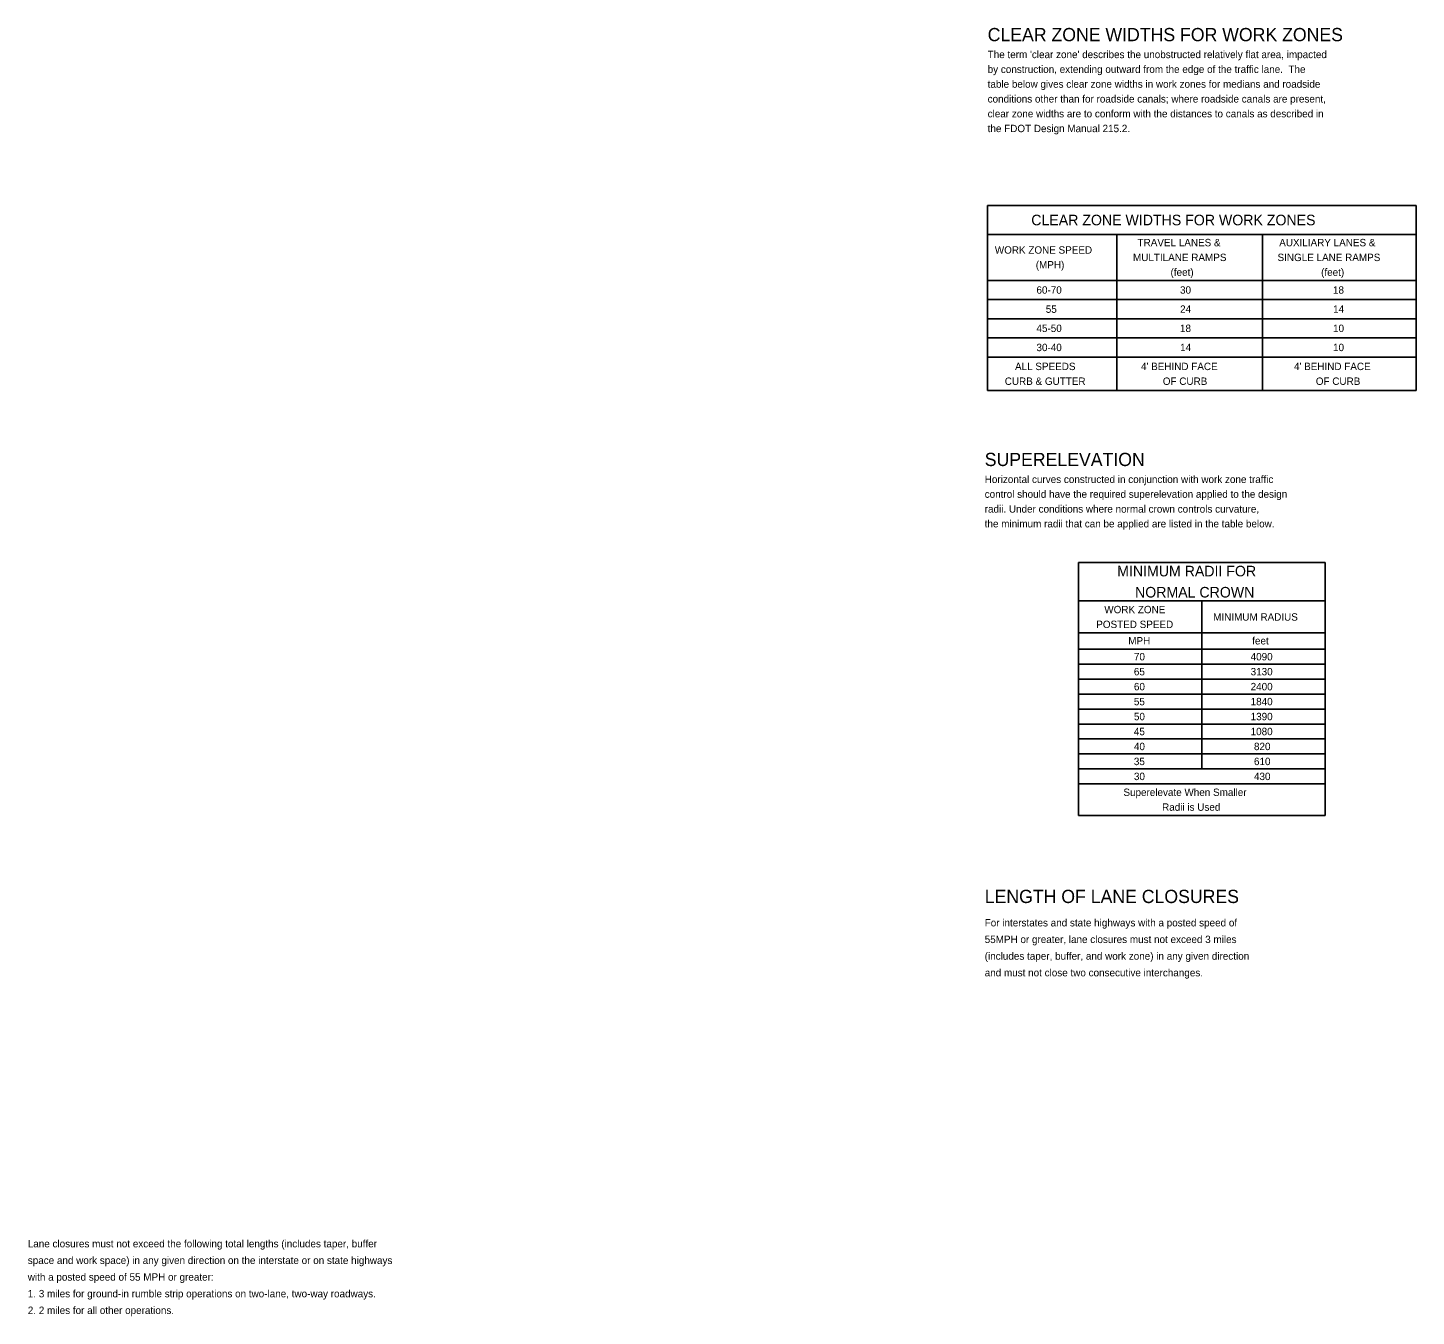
# Model space of a CAD drawing. Extents: x 9589 to 10706, y 9894 to 10509.
# Drawn here: x 9589 to 10246, y 9894 to 10504 of the extents above; entities that cross this region are included whole.
import ezdxf

# ---------------------------------------------------------------- set-up
doc = ezdxf.new("R2010")
doc.units = 0
doc.layers.add('PlotBorder_dp', color=7, linetype='Continuous')

msp = doc.modelspace()

# ---------------------------------------------------------------- linework, layer by layer
at = {"layer": 'PlotBorder_dp'}
for p, q in [((10246.24, 10419.67), (10043.48, 10419.67)), ((10043.48, 10332.21), (10043.48, 10419.67)), ((10246.24, 10332.23), (10246.24, 10419.67)), ((10246.24, 10406.08), (10043.48, 10406.08)), ((10104.52, 10332.21), (10104.52, 10406.08)), ((10173.51, 10332.23), (10173.51, 10406.08)), ((10246.24, 10384.31), (10043.48, 10384.31)), ((10246.24, 10375.26), (10043.48, 10375.26)), ((10246.24, 10366.2), (10043.48, 10366.2)), ((10246.24, 10357.14), (10043.48, 10357.14)), ((10246.24, 10348.08), (10043.48, 10348.08)), ((10246.24, 10332.23), (10043.48, 10332.23)), ((10086.5, 10250.92), (10203.22, 10250.92)), ((10086.5, 10131.28), (10086.5, 10250.92)), ((10203.22, 10250.92), (10203.22, 10131.28)), ((10086.5, 10232.79), (10203.22, 10232.79)), ((10144.86, 10232.79), (10144.86, 10153.6)), ((10086.5, 10217.59), (10203.22, 10217.59)), ((10086.5, 10209.92), (10203.22, 10209.92)), ((10086.5, 10202.84), (10203.22, 10202.84)), ((10086.5, 10195.76), (10203.22, 10195.76)), ((10086.5, 10188.69), (10203.22, 10188.69)), ((10086.5, 10181.61), (10203.22, 10181.61)), ((10086.5, 10174.53), (10203.22, 10174.53)), ((10086.5, 10167.46), (10203.22, 10167.46)), ((10086.5, 10160.38), (10203.22, 10160.38)), ((10086.5, 10153.3), (10203.22, 10153.3)), ((10086.5, 10146.22), (10203.22, 10146.22)), ((10203.22, 10131.28), (10086.5, 10131.28))]:
    msp.add_line(p, q, dxfattribs=at)

# ---------------------------------------------------------------- texts
for s, height, p in [('CLEAR ZONE WIDTHS FOR WORK ZONES', 6.25, (10043.48, 10497.44)), ("The term 'clear zone' describes the unobstructed relatively flat area, impacted", 3.5, (10043.48, 10489.42)), ('by construction, extending outward from the edge of the traffic lane.  The', 3.5, (10043.48, 10482.42)), ('table below gives clear zone widths in work zones for medians and roadside ', 3.5, (10043.48, 10475.42)), ('conditions other than for roadside canals; where roadside canals are present, ', 3.5, (10043.48, 10468.42)), ('clear zone widths are to conform with the distances to canals as described in ', 3.5, (10043.48, 10461.42)), ('the FDOT Design Manual 215.2. ', 3.5, (10043.48, 10454.42)), ('CLEAR ZONE WIDTHS FOR WORK ZONES', 5, (10064.11, 10410.38)), ('WORK ZONE SPEED', 3.5, (10046.87, 10396.95)), ('TRAVEL LANES &', 3.5, (10114.4, 10400.45)), ('AUXILIARY LANES & ', 3.5, (10181.42, 10400.45)), ('(MPH)', 3.5, (10066.24, 10389.95)), ('MULTILANE RAMPS', 3.5, (10112.24, 10393.45)), ('SINGLE LANE RAMPS', 3.5, (10180.61, 10393.45)), ('(feet)', 3.5, (10130, 10386.45)), ('(feet)', 3.5, (10201.24, 10386.45)), ('60-70', 3.5, (10066.57, 10378.03)), ('30', 3.5, (10134.49, 10378.03)), ('18', 3.5, (10206.85, 10378.03)), ('55', 3.5, (10070.98, 10368.98)), ('24', 3.5, (10134.52, 10368.98)), ('14', 3.5, (10206.9, 10368.98)), ('45-50', 3.5, (10066.57, 10359.92)), ('18', 3.5, (10134.46, 10359.92)), ('10', 3.5, (10206.88, 10359.92)), ('30-40', 3.5, (10066.57, 10350.86)), ('14', 3.5, (10134.52, 10350.86)), ('10', 3.5, (10206.88, 10350.86)), ('ALL SPEEDS', 3.5, (10056.42, 10341.9)), ("4' BEHIND FACE", 3.5, (10116.02, 10341.9)), ("4' BEHIND FACE", 3.5, (10188.41, 10341.9)), ('CURB & GUTTER ', 3.5, (10051.57, 10334.9)), ('OF CURB', 3.5, (10126.33, 10334.9)), ('OF CURB', 3.5, (10198.72, 10334.9)), ('SUPERELEVATION', 6.25, (10042.09, 10296.52)), ('Horizontal curves constructed in conjunction with work zone traffic', 3.5, (10042.09, 10288.5)), ('control should have the required superelevation applied to the design', 3.5, (10042.09, 10281.5)), ('radii. Under conditions where normal crown controls curvature,', 3.5, (10042.09, 10274.5)), ('the minimum radii that can be applied are listed in the table below.', 3.5, (10042.09, 10267.5)), ('MINIMUM RADII FOR', 5, (10104.76, 10244.36)), ('NORMAL CROWN', 5, (10113.2, 10234.36)), ('WORK ZONE', 3.5, (10098.67, 10226.91)), ('POSTED SPEED', 3.5, (10094.85, 10219.91)), ('MINIMUM RADIUS', 3.5, (10150.18, 10223.41)), ('MPH', 3.5, (10109.99, 10212.15)), ('feet', 3.5, (10168.64, 10212.15)), ('70', 3.5, (10112.68, 10204.63)), ('4090', 3.5, (10167.9, 10204.63)), ('65', 3.5, (10112.65, 10197.55)), ('3130', 3.5, (10167.9, 10197.55)), ('60', 3.5, (10112.68, 10190.48)), ('2400', 3.5, (10167.9, 10190.48)), ('55', 3.5, (10112.65, 10183.4)), ('1840', 3.5, (10167.9, 10183.4)), ('50', 3.5, (10112.68, 10176.32)), ('1390', 3.5, (10167.9, 10176.32)), ('45', 3.5, (10112.65, 10169.24)), ('1080', 3.5, (10167.9, 10169.24)), ('40', 3.5, (10112.68, 10162.17)), ('820', 3.5, (10169.47, 10162.17)), ('35', 3.5, (10112.65, 10155.09)), ('610', 3.5, (10169.47, 10155.09)), ('30', 3.5, (10112.68, 10148.01)), ('430', 3.5, (10169.47, 10148.01)), ('Superelevate When Smaller ', 3.5, (10107.7, 10140.5)), ('Radii is Used', 3.5, (10126, 10133.5)), ('LENGTH OF LANE CLOSURES', 6.25, (10042.09, 10089.87))]:
    msp.add_text(s, height=height, dxfattribs=at).set_placement(p)
for s, p in [('For interstates and state highways with a posted speed of ', (10042.08, 10078.81)), ('55MPH or greater, lane closures must not exceed 3 miles ', (10042.08, 10070.94)), ('(includes taper, buffer, and work zone) in any given direction ', (10042.08, 10063.06)), ('and must not close two consecutive interchanges.', (10042.08, 10055.19)), ('Lane closures must not exceed the following total lengths (includes taper, buffer ', (9589.36, 9927.03)), ('space and work space) in any given direction on the interstate or on state highways ', (9589.36, 9919.16)), ('with a posted speed of 55 MPH or greater:', (9589.36, 9911.28)), ('1. 3 miles for ground-in rumble strip operations on two-lane, two-way roadways.', (9589.36, 9903.41)), ('2. 2 miles for all other operations.', (9589.36, 9895.53))]:
    msp.add_text(s, height=3.5, rotation=359.99815, dxfattribs=at).set_placement(p)

doc.saveas('drawing.dxf')
